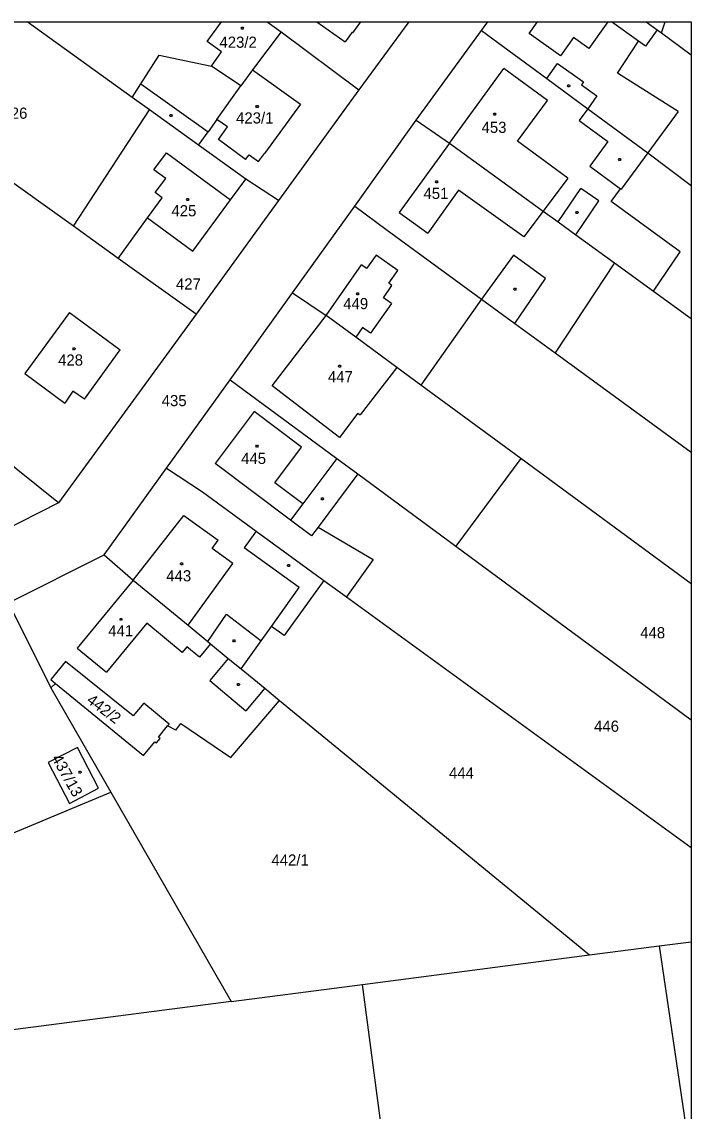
# Model space of a CAD drawing. Extents: x -639621 to -639329, y -1192893 to -1192488.
# Drawn here: x -639431.2 to -639329.3, y -1192653.7 to -1192487.8 of the extents above; entities that cross this region are included whole.
import ezdxf

# ---------------------------------------------------------------- set-up
doc = ezdxf.new("R2010")
doc.units = 0
for name, color, linetype in [('Vrstva 1', 7, 'Continuous'), ('Vrstva 2', 7, 'Continuous'), ('Vrstva 4', 7, 'Continuous'), ('Vrstva 5', 7, 'Continuous'), ('Vrstva 61', 7, 'Continuous')]:
    doc.layers.add(name, color=color, linetype=linetype)

msp = doc.modelspace()

# ---------------------------------------------------------------- linework, layer by layer
at = {"layer": 'Vrstva 1'}
for p, q in [((-639414.41, -1192499.35), (-639430.41, -1192487.83)), ((-639403.02, -1192490.84), (-639400.83, -1192487.83)), ((-639393.87, -1192487.83), (-639391.71, -1192489.38)), ((-639372.29, -1192487.83), (-639379.92, -1192498.19)), ((-639361.21, -1192489.14), (-639360.26, -1192487.83)), ((-639336.13, -1192487.83), (-639334.43, -1192489.07)), ((-639333.81, -1192489.52), (-639333.23, -1192487.83)), ((-639391.71, -1192489.38), (-639396.11, -1192495.13)), ((-639391.71, -1192489.38), (-639379.92, -1192498.19)), ((-639371.16, -1192502.83), (-639361.21, -1192489.14)), ((-639361.21, -1192489.14), (-639351.24, -1192496.49)), ((-639334.43, -1192489.07), (-639336.21, -1192491.56)), ((-639334.43, -1192489.07), (-639333.81, -1192489.52)), ((-639333.81, -1192489.52), (-639329.26, -1192492.88)), ((-639400.8, -1192492.43), (-639403.02, -1192490.84)), ((-639340.48, -1192495.66), (-639337.31, -1192490.77)), ((-639336.21, -1192491.56), (-639337.31, -1192490.77)), ((-639413.09, -1192497.28), (-639410.3, -1192492.89)), ((-639410.3, -1192492.89), (-639402.34, -1192494.6)), ((-639402.34, -1192494.6), (-639400.8, -1192492.43)), ((-639397.86, -1192497.59), (-639402.34, -1192494.6)), ((-639396.11, -1192495.13), (-639397.86, -1192497.59)), ((-639331.24, -1192501.49), (-639340.48, -1192495.66)), ((-639414.41, -1192499.35), (-639413.09, -1192497.28)), ((-639351.24, -1192496.49), (-639345.02, -1192501.08)), ((-639379.92, -1192498.19), (-639392.16, -1192515.05)), ((-639411.8, -1192501.23), (-639414.41, -1192499.35)), ((-639423.39, -1192518.97), (-639411.8, -1192501.23)), ((-639404.31, -1192506.62), (-639411.8, -1192501.23)), ((-639345.02, -1192501.08), (-639335.89, -1192507.81)), ((-639331.24, -1192501.49), (-639335.89, -1192507.81)), ((-639380.52, -1192515.93), (-639371.16, -1192502.83)), ((-639371.16, -1192502.83), (-639366.08, -1192506.31)), ((-639423.39, -1192518.97), (-639443.48, -1192504.61)), ((-639397.1, -1192511.81), (-639404.31, -1192506.62)), ((-639366.08, -1192506.31), (-639351.83, -1192516.65)), ((-639335.89, -1192507.81), (-639339.95, -1192513.32)), ((-639335.89, -1192507.81), (-639329.26, -1192512.76)), ((-639399.45, -1192514.92), (-639397.1, -1192511.81)), ((-639392.16, -1192515.05), (-639397.1, -1192511.81)), ((-639341.47, -1192515.19), (-639340.05, -1192513.25)), ((-639340.05, -1192513.25), (-639339.95, -1192513.32)), ((-639405.18, -1192522.77), (-639399.45, -1192514.92)), ((-639392.16, -1192515.05), (-639404.68, -1192532.35)), ((-639330.96, -1192522.88), (-639341.47, -1192515.19)), ((-639390.01, -1192529.12), (-639380.52, -1192515.93)), ((-639380.52, -1192515.93), (-639375.58, -1192519.55)), ((-639351.83, -1192516.65), (-639349.54, -1192518.31)), ((-639416.56, -1192523.86), (-639412.11, -1192517.69)), ((-639412.11, -1192517.69), (-639405.18, -1192522.77)), ((-639349.54, -1192518.31), (-639346.86, -1192520.25)), ((-639416.56, -1192523.86), (-639423.39, -1192518.97)), ((-639375.58, -1192519.55), (-639361.19, -1192530.05)), ((-639346.86, -1192520.25), (-639340.93, -1192524.55)), ((-639404.68, -1192532.35), (-639416.56, -1192523.86)), ((-639334.99, -1192528.86), (-639330.96, -1192522.88)), ((-639340.93, -1192524.55), (-639350, -1192538.22)), ((-639340.93, -1192524.55), (-639334.99, -1192528.86)), ((-639334.99, -1192528.86), (-639329.26, -1192533.02)), ((-639399.52, -1192542.35), (-639390.01, -1192529.12)), ((-639390.01, -1192529.12), (-639384.88, -1192532.55)), ((-639361.19, -1192530.05), (-639370.46, -1192543.15)), ((-639361.19, -1192530.05), (-639356.11, -1192533.76)), ((-639423.97, -1192532.09), (-639430.76, -1192541.4)), ((-639423.97, -1192532.09), (-639416.25, -1192537.78)), ((-639404.68, -1192532.35), (-639425.67, -1192561.08)), ((-639380.37, -1192535.86), (-639384.88, -1192532.55)), ((-639356.11, -1192533.76), (-639350, -1192538.22)), ((-639374.13, -1192540.45), (-639380.37, -1192535.86)), ((-639421.67, -1192545.27), (-639416.25, -1192537.78)), ((-639350, -1192538.22), (-639329.26, -1192553.36)), ((-639370.46, -1192543.15), (-639374.13, -1192540.45)), ((-639430.76, -1192541.4), (-639424.71, -1192545.89)), ((-639409.19, -1192555.81), (-639399.52, -1192542.35)), ((-639399.52, -1192542.35), (-639383.27, -1192554.32)), ((-639355.24, -1192554.33), (-639370.46, -1192543.15)), ((-639425.67, -1192561.08), (-639447, -1192544.01)), ((-639423.45, -1192544.05), (-639424.71, -1192545.89)), ((-639421.67, -1192545.27), (-639423.45, -1192544.05)), ((-639383.27, -1192554.32), (-639380.06, -1192556.68)), ((-639355.24, -1192554.33), (-639365.14, -1192567.68)), ((-639329.26, -1192573.4), (-639355.24, -1192554.33)), ((-639418.68, -1192568.97), (-639409.19, -1192555.81)), ((-639409.19, -1192555.81), (-639403.73, -1192559.41)), ((-639380.06, -1192556.68), (-639386.12, -1192564.77)), ((-639380.06, -1192556.68), (-639365.14, -1192567.68)), ((-639403.73, -1192559.41), (-639395.53, -1192565.38)), ((-639425.67, -1192561.08), (-639434.43, -1192565.52)), ((-639386.12, -1192564.77), (-639377.7, -1192569.71)), ((-639395.53, -1192565.38), (-639385.22, -1192572.88)), ((-639365.14, -1192567.68), (-639329.26, -1192594.12)), ((-639433.26, -1192576.32), (-639418.68, -1192568.97)), ((-639418.68, -1192568.97), (-639414.27, -1192572.85)), ((-639377.7, -1192569.71), (-639381.78, -1192575.38)), ((-639414.27, -1192572.85), (-639405.9, -1192579.72)), ((-639385.22, -1192572.88), (-639391.28, -1192581.27)), ((-639385.22, -1192572.88), (-639381.78, -1192575.38)), ((-639433.26, -1192576.32), (-639426.82, -1192589.24)), ((-639381.78, -1192575.38), (-639329.26, -1192613.57)), ((-639405.9, -1192579.72), (-639402.9, -1192582.2)), ((-639394.77, -1192582.08), (-639393.2, -1192579.88)), ((-639391.28, -1192581.27), (-639393.2, -1192579.88)), ((-639402.9, -1192582.2), (-639402.48, -1192582.54)), ((-639402.48, -1192582.54), (-639399.79, -1192584.75)), ((-639397.82, -1192586.37), (-639394.77, -1192582.08)), ((-639424.59, -1192585.22), (-639426.83, -1192587.99)), ((-639414.29, -1192593.52), (-639424.59, -1192585.22)), ((-639399.79, -1192584.75), (-639397.82, -1192586.37)), ((-639397.82, -1192586.37), (-639394.23, -1192589.31)), ((-639426.83, -1192587.99), (-639426.11, -1192588.58)), ((-639426.82, -1192589.24), (-639426.11, -1192588.58)), ((-639426.82, -1192589.24), (-639417.68, -1192605.12)), ((-639426.11, -1192588.58), (-639412.71, -1192599.56)), ((-639394.23, -1192589.31), (-639391.98, -1192591.15)), ((-639412.65, -1192591.55), (-639414.29, -1192593.52)), ((-639408.8, -1192594.75), (-639412.65, -1192591.55)), ((-639399.41, -1192599.85), (-639391.98, -1192591.15)), ((-639391.98, -1192591.15), (-639344.75, -1192629.91)), ((-639410.43, -1192596.75), (-639409.04, -1192595.05)), ((-639409.04, -1192595.05), (-639408.8, -1192594.75)), ((-639407.79, -1192595.66), (-639409.04, -1192595.05)), ((-639407.79, -1192595.66), (-639407, -1192594.65)), ((-639407, -1192594.65), (-639399.41, -1192599.85)), ((-639410.19, -1192596.95), (-639410.43, -1192596.75)), ((-639422.78, -1192598.3), (-639427.24, -1192600.6)), ((-639419.54, -1192604.54), (-639422.78, -1192598.3)), ((-639412.71, -1192599.56), (-639410.98, -1192597.44)), ((-639410.98, -1192597.44), (-639410.74, -1192597.63)), ((-639410.74, -1192597.63), (-639410.19, -1192596.95)), ((-639427.24, -1192600.6), (-639424, -1192606.85)), ((-639442.23, -1192615.33), (-639417.68, -1192605.12)), ((-639424, -1192606.85), (-639419.54, -1192604.54)), ((-639417.68, -1192605.12), (-639399.34, -1192636.99)), ((-639334.13, -1192628.53), (-639329.26, -1192627.9)), ((-639379.36, -1192634.4), (-639344.75, -1192629.91)), ((-639344.75, -1192629.91), (-639334.13, -1192628.53)), ((-639334.13, -1192628.53), (-639329.26, -1192661.57)), ((-639399.34, -1192636.99), (-639379.36, -1192634.4)), ((-639374.53, -1192670.58), (-639379.36, -1192634.4)), ((-639399.34, -1192636.99), (-639439.54, -1192642.21))]:
    msp.add_line(p, q, dxfattribs=at)
at = {"layer": 'Vrstva 4'}
for p, q in [((-639386.29, -1192487.83), (-639381.99, -1192490.91)), ((-639380.8, -1192489.51), (-639379.61, -1192487.83)), ((-639353.95, -1192489.62), (-639352.67, -1192487.83)), ((-639341.97, -1192487.83), (-639344.88, -1192491.9)), ((-639337.31, -1192490.77), (-639341.43, -1192487.83)), ((-639380.93, -1192489.42), (-639381.99, -1192490.91)), ((-639380.8, -1192489.51), (-639380.93, -1192489.42)), ((-639349.17, -1192493.03), (-639353.95, -1192489.62)), ((-639347.19, -1192490.25), (-639349.17, -1192493.03)), ((-639344.88, -1192491.9), (-639347.19, -1192490.25)), ((-639396.11, -1192495.13), (-639388.79, -1192500.36)), ((-639366.08, -1192506.31), (-639357.83, -1192494.94)), ((-639351.18, -1192499.82), (-639357.83, -1192494.94)), ((-639351.24, -1192496.49), (-639349.62, -1192494.18)), ((-639349.62, -1192494.18), (-639345.67, -1192496.97)), ((-639413.09, -1192497.28), (-639402.86, -1192504.59)), ((-639345.67, -1192496.97), (-639346, -1192497.44)), ((-639401.51, -1192502.7), (-639397.86, -1192497.59)), ((-639346, -1192497.44), (-639343.63, -1192499.11)), ((-639388.79, -1192500.36), (-639394.27, -1192507.87)), ((-639355.74, -1192506.03), (-639351.18, -1192499.82)), ((-639343.63, -1192499.11), (-639345.02, -1192501.08)), ((-639345.02, -1192501.08), (-639346.34, -1192502.88)), ((-639401.51, -1192502.7), (-639402.86, -1192504.59)), ((-639399.92, -1192503.83), (-639401.51, -1192502.7)), ((-639401.29, -1192505.75), (-639399.92, -1192503.83)), ((-639346.34, -1192502.88), (-639341.98, -1192506.07)), ((-639404.31, -1192506.62), (-639402.86, -1192504.59)), ((-639397.14, -1192508.81), (-639401.29, -1192505.75)), ((-639366.08, -1192506.31), (-639373.76, -1192516.88)), ((-639348.08, -1192511.65), (-639355.74, -1192506.03)), ((-639341.98, -1192506.07), (-639344.73, -1192509.82)), ((-639411.12, -1192510.35), (-639409.22, -1192507.79)), ((-639409.22, -1192507.79), (-639399.45, -1192514.92)), ((-639397.14, -1192508.81), (-639396.6, -1192508.07)), ((-639396.6, -1192508.07), (-639395.18, -1192509.11)), ((-639395.18, -1192509.11), (-639394.27, -1192507.87)), ((-639409.31, -1192511.7), (-639411.12, -1192510.35)), ((-639344.73, -1192509.82), (-639340.05, -1192513.25)), ((-639410.91, -1192513.84), (-639409.31, -1192511.7)), ((-639348.08, -1192511.65), (-639351.83, -1192516.65)), ((-639409.84, -1192514.64), (-639410.91, -1192513.84)), ((-639364.7, -1192513.45), (-639369.37, -1192520.01)), ((-639354.74, -1192520.55), (-639364.7, -1192513.45)), ((-639349.54, -1192518.31), (-639346.06, -1192513.21)), ((-639343.33, -1192515.08), (-639346.06, -1192513.21)), ((-639412.11, -1192517.69), (-639409.84, -1192514.64)), ((-639346.86, -1192520.25), (-639343.33, -1192515.08)), ((-639373.76, -1192516.88), (-639369.37, -1192520.01)), ((-639351.83, -1192516.65), (-639354.74, -1192520.55)), ((-639377.28, -1192523.36), (-639378.71, -1192525.4)), ((-639373.96, -1192525.68), (-639377.28, -1192523.36)), ((-639356.34, -1192523.36), (-639361.19, -1192530.05)), ((-639351.46, -1192526.9), (-639356.34, -1192523.36)), ((-639384.88, -1192532.55), (-639379.49, -1192524.86)), ((-639378.71, -1192525.4), (-639379.49, -1192524.86)), ((-639375.33, -1192527.65), (-639373.96, -1192525.68)), ((-639356.11, -1192533.76), (-639351.46, -1192526.9)), ((-639376.16, -1192529.86), (-639374.85, -1192527.98)), ((-639374.85, -1192527.98), (-639375.33, -1192527.65)), ((-639374.93, -1192530.72), (-639376.16, -1192529.86)), ((-639374.93, -1192530.72), (-639378.1, -1192535.24)), ((-639393.11, -1192543.27), (-639384.88, -1192532.55)), ((-639379.33, -1192534.38), (-639380.37, -1192535.86)), ((-639378.1, -1192535.24), (-639379.33, -1192534.38)), ((-639374.13, -1192540.45), (-639379.7, -1192547.69)), ((-639382.87, -1192551.13), (-639393.11, -1192543.27)), ((-639395.87, -1192547.18), (-639401.79, -1192555.08)), ((-639388.64, -1192552.6), (-639395.87, -1192547.18)), ((-639380.03, -1192547.44), (-639382.87, -1192551.13)), ((-639380.03, -1192547.44), (-639379.7, -1192547.69)), ((-639392.71, -1192558.03), (-639388.64, -1192552.6)), ((-639390.29, -1192563.7), (-639401.79, -1192555.08)), ((-639383.27, -1192554.32), (-639388.44, -1192561.22)), ((-639388.44, -1192561.22), (-639392.71, -1192558.03)), ((-639388.44, -1192561.22), (-639390.29, -1192563.7)), ((-639414.27, -1192572.85), (-639406.54, -1192562.99)), ((-639406.54, -1192562.99), (-639401.32, -1192566.76)), ((-639387.1, -1192566.08), (-639390.29, -1192563.7)), ((-639386.12, -1192564.77), (-639387.1, -1192566.08)), ((-639402.23, -1192568.02), (-639401.32, -1192566.76)), ((-639395.53, -1192565.38), (-639397.36, -1192567.91)), ((-639399.08, -1192570.29), (-639402.23, -1192568.02)), ((-639388.98, -1192573.96), (-639397.36, -1192567.91)), ((-639405.9, -1192579.72), (-639399.08, -1192570.29)), ((-639414.27, -1192572.85), (-639422.82, -1192583.19)), ((-639393.2, -1192579.88), (-639388.98, -1192573.96)), ((-639402.9, -1192582.2), (-639400.07, -1192578.01)), ((-639400.07, -1192578.01), (-639394.77, -1192582.08)), ((-639412.22, -1192579.4), (-639418.35, -1192586.86)), ((-639406.81, -1192583.84), (-639412.22, -1192579.4)), ((-639422.82, -1192583.19), (-639418.35, -1192586.86)), ((-639406.11, -1192582.99), (-639406.81, -1192583.84)), ((-639404.16, -1192584.58), (-639406.11, -1192582.99)), ((-639402.48, -1192582.54), (-639404.16, -1192584.58)), ((-639399.79, -1192584.75), (-639402.62, -1192588.13)), ((-639402.62, -1192588.13), (-639397.1, -1192592.74)), ((-639394.23, -1192589.31), (-639397.1, -1192592.74))]:
    msp.add_line(p, q, dxfattribs=at)
at = {"layer": 'Vrstva 5'}
for points in [[(-639397.55, -1192488.64), (-639397.46, -1192488.79), (-639397.55, -1192488.94), (-639397.73, -1192488.94), (-639397.82, -1192488.79), (-639397.73, -1192488.64)], [(-639347.82, -1192497.42), (-639347.73, -1192497.57), (-639347.82, -1192497.72), (-639348, -1192497.72), (-639348.09, -1192497.57), (-639348, -1192497.42)], [(-639395.3, -1192500.56), (-639395.21, -1192500.71), (-639395.3, -1192500.86), (-639395.48, -1192500.86), (-639395.57, -1192500.71), (-639395.48, -1192500.56)], [(-639408.44, -1192501.93), (-639408.35, -1192502.08), (-639408.44, -1192502.23), (-639408.62, -1192502.23), (-639408.71, -1192502.08), (-639408.62, -1192501.93)], [(-639359.12, -1192501.74), (-639359.03, -1192501.89), (-639359.12, -1192502.04), (-639359.3, -1192502.04), (-639359.39, -1192501.89), (-639359.3, -1192501.74)], [(-639340.08, -1192508.65), (-639339.99, -1192508.8), (-639340.08, -1192508.95), (-639340.26, -1192508.95), (-639340.35, -1192508.8), (-639340.26, -1192508.65)], [(-639367.95, -1192512.03), (-639367.86, -1192512.18), (-639367.95, -1192512.33), (-639368.13, -1192512.33), (-639368.22, -1192512.18), (-639368.13, -1192512.03)], [(-639405.89, -1192514.74), (-639405.8, -1192514.89), (-639405.89, -1192515.04), (-639406.07, -1192515.04), (-639406.16, -1192514.89), (-639406.07, -1192514.74)], [(-639346.56, -1192516.71), (-639346.47, -1192516.86), (-639346.56, -1192517.01), (-639346.74, -1192517.01), (-639346.83, -1192516.86), (-639346.74, -1192516.71)], [(-639356.04, -1192528.37), (-639355.95, -1192528.52), (-639356.04, -1192528.67), (-639356.22, -1192528.67), (-639356.31, -1192528.52), (-639356.22, -1192528.37)], [(-639379.99, -1192529.09), (-639379.9, -1192529.24), (-639379.99, -1192529.39), (-639380.17, -1192529.39), (-639380.26, -1192529.24), (-639380.17, -1192529.09)], [(-639423.18, -1192537.48), (-639423.09, -1192537.63), (-639423.18, -1192537.78), (-639423.36, -1192537.78), (-639423.45, -1192537.63), (-639423.36, -1192537.48)], [(-639382.75, -1192540.13), (-639382.66, -1192540.28), (-639382.75, -1192540.43), (-639382.93, -1192540.43), (-639383.02, -1192540.28), (-639382.93, -1192540.13)], [(-639395.33, -1192552.31), (-639395.24, -1192552.46), (-639395.33, -1192552.61), (-639395.51, -1192552.61), (-639395.6, -1192552.46), (-639395.51, -1192552.31)], [(-639385.37, -1192560.3), (-639385.28, -1192560.45), (-639385.37, -1192560.6), (-639385.55, -1192560.6), (-639385.64, -1192560.45), (-639385.55, -1192560.3)], [(-639406.82, -1192570.23), (-639406.73, -1192570.38), (-639406.82, -1192570.53), (-639407, -1192570.53), (-639407.09, -1192570.38), (-639407, -1192570.23)], [(-639390.52, -1192570.47), (-639390.43, -1192570.62), (-639390.52, -1192570.77), (-639390.7, -1192570.77), (-639390.79, -1192570.62), (-639390.7, -1192570.47)], [(-639416.05, -1192578.66), (-639415.96, -1192578.81), (-639416.05, -1192578.96), (-639416.23, -1192578.96), (-639416.32, -1192578.81), (-639416.23, -1192578.66)], [(-639398.83, -1192581.92), (-639398.74, -1192582.07), (-639398.83, -1192582.22), (-639399.01, -1192582.22), (-639399.1, -1192582.07), (-639399.01, -1192581.92)], [(-639398.15, -1192588.56), (-639398.06, -1192588.71), (-639398.15, -1192588.86), (-639398.33, -1192588.86), (-639398.42, -1192588.71), (-639398.33, -1192588.56)], [(-639422.27, -1192601.91), (-639422.18, -1192602.06), (-639422.27, -1192602.21), (-639422.45, -1192602.21), (-639422.54, -1192602.06), (-639422.45, -1192601.91)]]:
    msp.add_lwpolyline(points, close=True, dxfattribs=at)
at = {"layer": 'Vrstva 61'}
for points in [[(-639621.26, -1192487.83), (-639329.26, -1192487.83)], [(-639329.26, -1192487.83), (-639329.26, -1192893.33)]]:
    msp.add_lwpolyline(points, dxfattribs=at)

# ---------------------------------------------------------------- texts
at = {"layer": 'Vrstva 2'}
for s, p in [('423/2', (-639401.13, -1192491.79)), ('426', (-639434.19, -1192502.6)), ('423/1', (-639398.6, -1192503.32)), ('453', (-639361.2, -1192504.75)), ('451', (-639370.05, -1192514.81)), ('425', (-639408.45, -1192517.45)), ('427', (-639407.76, -1192528.6)), ('449', (-639382.27, -1192531.59)), ('428', (-639425.71, -1192540.18)), ('447', (-639384.6, -1192542.72)), ('435', (-639409.93, -1192546.36)), ('445', (-639397.83, -1192555.16)), ('443', (-639409.23, -1192573.03)), ('441', (-639418.07, -1192581.4)), ('448', (-639337.03, -1192581.7)), ('446', (-639344.06, -1192595.93)), ('444', (-639366.16, -1192603.05)), ('442/1', (-639393.22, -1192616.31))]:
    msp.add_text(s, height=1.7, dxfattribs=at).set_placement(p)
for s, rotation, p in [('442/2', 323.0909, (-639421.5, -1192591.4)), ('437/13', 299.1986, (-639426.76, -1192599.94))]:
    msp.add_text(s, height=1.7, rotation=rotation, dxfattribs=at).set_placement(p)

doc.saveas('drawing.dxf')
